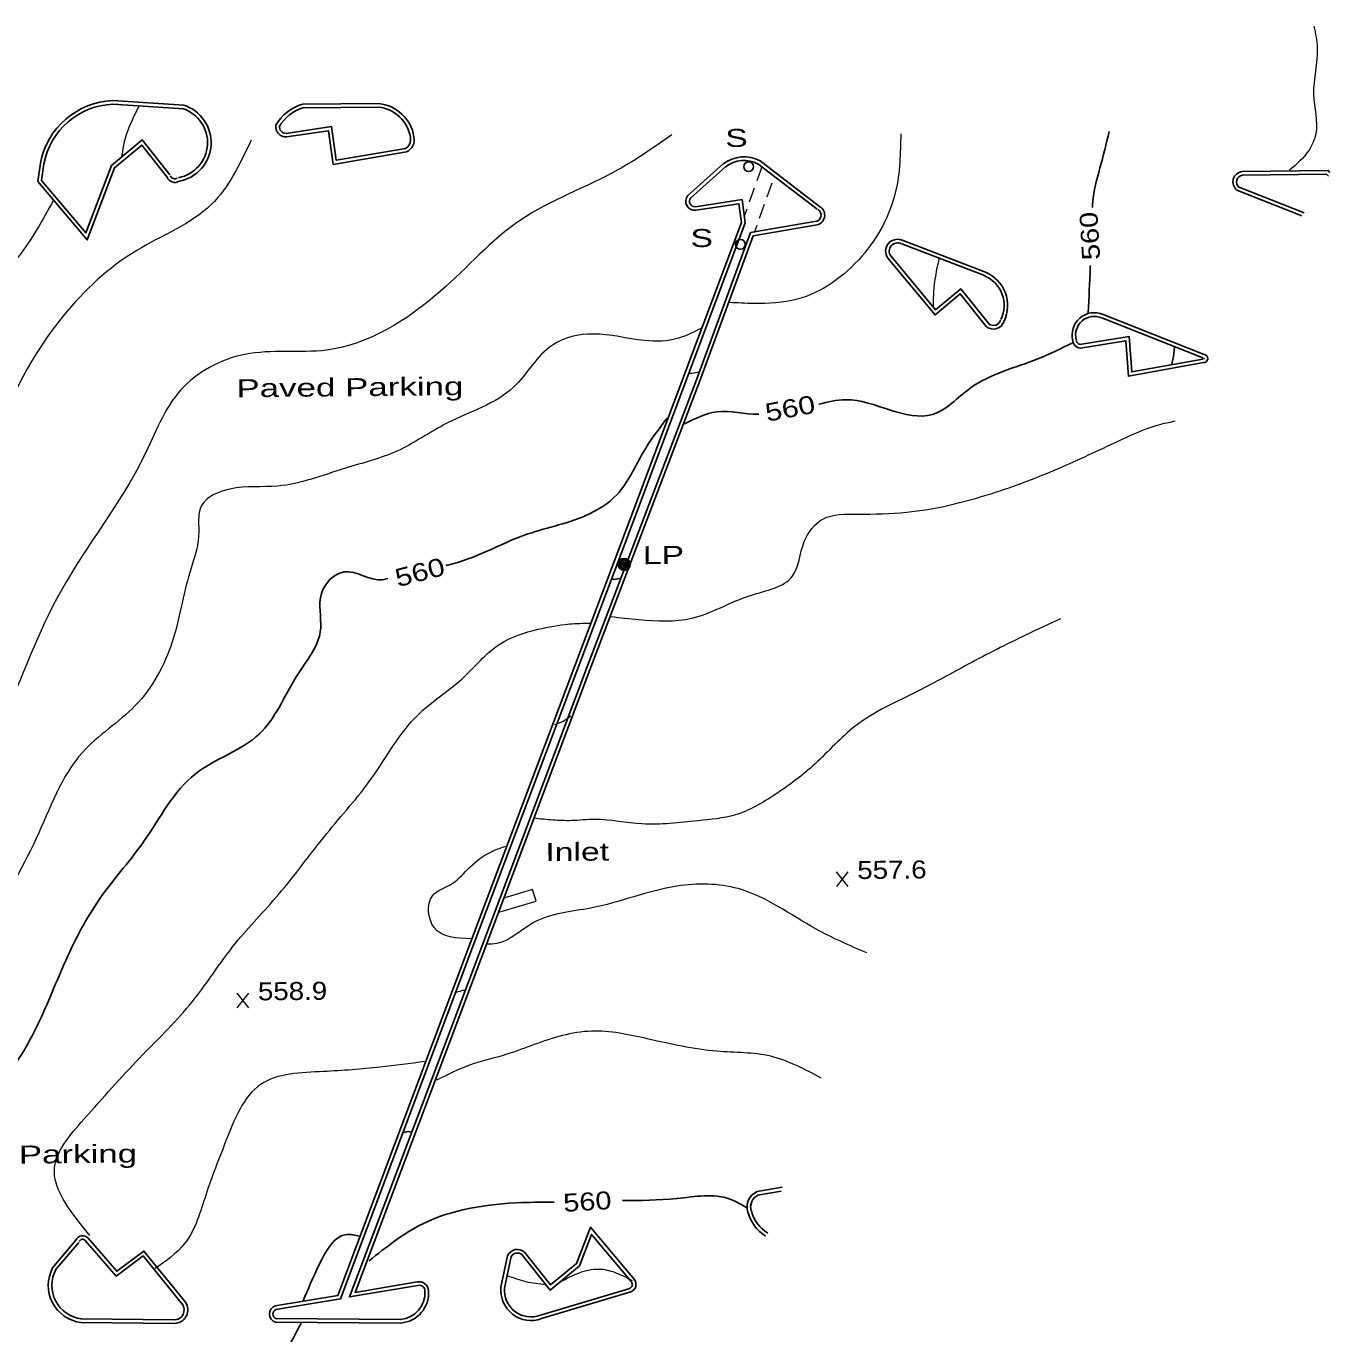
# Model space of a CAD drawing. Extents: x 2361708 to 2370558, y 6977955 to 6991887.
# Drawn here: x 2366902.2 to 2367249.9, y 6987347 to 6987695.7 of the extents above; entities that cross this region are included whole.
import ezdxf
from ezdxf.enums import TextEntityAlignment as Align

# ---------------------------------------------------------------- set-up
doc = ezdxf.new("R2010")
doc.units = 0
doc.header["$LTSCALE"] = 1.9
for name, color, linetype, lineweight in [('13', 7, 'Continuous', 13), ('2', 7, 'Continuous', 25), ('20', 7, 'Continuous', 25), ('21', 7, 'Continuous', 25), ('31', 7, 'Continuous', 13), ('35', 7, 'Continuous', 13), ('9', 7, 'Continuous', 13)]:
    doc.layers.add(name, color=color, linetype=linetype, lineweight=lineweight)

msp = doc.modelspace()

# ---------------------------------------------------------------- linework, layer by layer
at = {"layer": '13'}
for p, q in [((2367097.132, 6987654.501), (2367098.457, 6987658.234)), ((2367095.116, 6987648.841), (2367096.46, 6987652.614)), ((2367099.804, 6987650.136), (2367101.138, 6987653.909)), ((2367097.788, 6987644.477), (2367099.132, 6987648.25)), ((2367093.772, 6987645.068), (2367094.444, 6987646.955)), ((2367096.444, 6987640.704), (2367097.116, 6987642.59))]:
    msp.add_line(p, q, dxfattribs=at)
at = {"layer": '2'}
for p, q in [((2366944.213, 6987674.606), (2366925.361, 6987675.836)), ((2366944.152, 6987673.645), (2366925.3, 6987674.876)), ((2366996.222, 6987675.031), (2366975.973, 6987674.879)), ((2366996.231, 6987674.071), (2366975.981, 6987673.919)), ((2367088.11, 6987658.935), (2367078.69, 6987650.505)), ((2367088.746, 6987658.221), (2367079.326, 6987649.791)), ((2367113.186, 6987646.853), (2367097.32, 6987658.973)), ((2367113.769, 6987647.619), (2367097.903, 6987659.738)), ((2367225.073, 6987651.938), (2367242.389, 6987645.113)), ((2367225.425, 6987652.832), (2367242.991, 6987645.909)), ((2367157.726, 6987629.156), (2367135.725, 6987637.597)), ((2367158.068, 6987630.049), (2367136.066, 6987638.491)), ((2367215.968, 6987607.24), (2367189.035, 6987617.884)), ((2367216.319, 6987608.133), (2367189.387, 6987618.777)), ((2367103.837, 6987386.151), (2367097.178, 6987384.978)), ((2367103.507, 6987385.118), (2367097.347, 6987384.03)), ((2366915.482, 6987372.028), (2366909.253, 6987364.608)), ((2366916.218, 6987371.415), (2366909.988, 6987363.995)), ((2367030.607, 6987367.874), (2367028.827, 6987359.446)), ((2367031.55, 6987367.673), (2367029.769, 6987359.245)), ((2367039.379, 6987352.016), (2367063.192, 6987359.163)), ((2367039.658, 6987351.099), (2367063.471, 6987358.246)), ((2366916.821, 6987350.05), (2366941.715, 6987349.807)), ((2366916.832, 6987351.01), (2366941.726, 6987350.766)), ((2366968.713, 6987350.143), (2367002.117, 6987349.921)), ((2366968.724, 6987351.104), (2367002.128, 6987350.882))]:
    msp.add_line(p, q, dxfattribs=at)
for points in [[(2366971.516, 6987667.085), (2366983.61, 6987668.881), (2366984.905, 6987659.933), (2367003.456, 6987663.08)], [(2366906.95, 6987659.011), (2366906.342, 6987654.525), (2366918.167, 6987640.546), (2366924.946, 6987658.482), (2366933.151, 6987665.351), (2366940.55, 6987656.03)], [(2366971.655, 6987666.137), (2366982.8, 6987667.793), (2366984.096, 6987658.825), (2367003.615, 6987662.131)], [(2366905.999, 6987659.142), (2366905.336, 6987654.235), (2366918.484, 6987638.68), (2366925.752, 6987657.91), (2366933.014, 6987663.979), (2366939.796, 6987655.433)], [(2367249.859, 6987656.695), (2367249.414, 6987657.201), (2367226.486, 6987656.902)], [(2367249.509, 6987655.641), (2367248.983, 6987656.236), (2367226.495, 6987655.942)], [(2367080.807, 6987646.595), (2367092.291, 6987648.334), (2367092.939, 6987643.31), (2367062.344, 6987561.696), (2367020.712, 6987451.394), (2366985.366, 6987357.252), (2366968.622, 6987354.493)], [(2367080.668, 6987647.543), (2367093.12, 6987649.433), (2367093.92, 6987643.2), (2367063.247, 6987561.354), (2367021.615, 6987451.052), (2366986.074, 6987356.399), (2366968.781, 6987353.545)], [(2367006.652, 6987359.935), (2366988.42, 6987356.862), (2367014.348, 6987425.512), (2367051.598, 6987524.411), (2367080.926, 6987601.414), (2367095.394, 6987640.654), (2367112.457, 6987643.586)], [(2367006.493, 6987360.884), (2366989.909, 6987358.086), (2367015.241, 6987425.17), (2367052.491, 6987524.07), (2367081.83, 6987601.072), (2367096.102, 6987639.8), (2367112.616, 6987642.638)], [(2367132.031, 6987633.792), (2367144.575, 6987618.69), (2367151.283, 6987624.274), (2367158.326, 6987615.542)], [(2367132.765, 6987634.409), (2367144.703, 6987620.042), (2367151.419, 6987625.636), (2367159.07, 6987616.148)], [(2367183.742, 6987610.873), (2367196.343, 6987612.923), (2367197.033, 6987603.499), (2367215.991, 6987606.91)], [(2367183.901, 6987609.924), (2367195.464, 6987611.805), (2367196.153, 6987602.36), (2367216.16, 6987605.962)], [(2366944.671, 6987355.485), (2366933.611, 6987369.12), (2366926.382, 6987363.722), (2366918.708, 6987372.538)], [(2367063.575, 6987360.957), (2367052.974, 6987373.567), (2367049.774, 6987365.166), (2367041.925, 6987358.721), (2367034.354, 6987368.189)], [(2367064.309, 6987361.574), (2367052.656, 6987375.434), (2367048.969, 6987365.749), (2367042.072, 6987360.083), (2367035.109, 6987368.786)], [(2366943.927, 6987354.878), (2366933.443, 6987367.799), (2366926.244, 6987362.42), (2366917.984, 6987371.911)]]:
    msp.add_lwpolyline(points, dxfattribs=at)
for centre, radius, start, end in [((2366926.161, 6987655.334), 20.519, 92.23486, 169.30474), ((2366926.161, 6987655.334), 19.559, 92.23486, 169.30474), ((2366941.072, 6987664.62), 9.509, 280.70452, 72.53644), ((2366941.072, 6987664.62), 10.469, 280.70452, 72.53644), ((2366979.236, 6987663.354), 11.978, 105.81197, 150.45573), ((2366979.236, 6987663.354), 11.018, 105.81197, 150.45573), ((2366995.2, 6987664.53), 9.591, 9.16298, 84.4425), ((2366995.2, 6987664.53), 10.551, 9.16298, 84.4425), ((2366971.497, 6987668.847), 2.713, 171.23755, 273.34708), ((2366971.497, 6987668.847), 1.753, 171.23755, 273.34708), ((2367002.064, 6987665.422), 2.678, 295.23741, 12.51175), ((2367002.064, 6987665.422), 3.638, 295.23741, 12.51175), ((2367093.618, 6987651.876), 8.954, 61.41106, 127.96633), ((2367093.618, 6987651.876), 7.994, 61.41106, 127.96633), ((2366941.864, 6987656.226), 2.215, 200.96378, 301.34614), ((2366941.864, 6987656.226), 1.255, 200.96378, 301.34614), ((2367226.803, 6987654.129), 2.791, 96.53229, 231.69698), ((2367226.803, 6987654.129), 1.831, 96.53229, 231.69698), ((2367080.5, 6987648.958), 2.381, 139.48847, 277.39994), ((2367080.5, 6987648.958), 1.421, 139.48847, 277.39994), ((2367112.495, 6987645.289), 1.694, 272.62187, 61.32494), ((2367112.495, 6987645.289), 2.655, 272.62187, 61.32494), ((2367134.583, 6987635.683), 3.175, 62.14387, 216.54513), ((2367134.583, 6987635.683), 2.215, 62.14387, 216.54513), ((2367154.39, 6987621.229), 8.596, 334.03887, 67.36425), ((2367154.39, 6987621.229), 9.556, 334.03887, 67.36425), ((2367160.136, 6987617.896), 2.97, 232.45964, 343.36409), ((2367160.136, 6987617.896), 2.01, 232.45964, 343.36409), ((2367187.025, 6987613.36), 5.91, 66.44284, 195.20793), ((2367187.025, 6987613.36), 4.949, 66.44284, 195.20793), ((2367183.402, 6987611.951), 2.084, 183.87025, 283.82028), ((2367183.402, 6987611.951), 1.124, 183.87025, 283.82028), ((2367216.199, 6987607.051), 1.091, 267.9356, 83.66717), ((2367216.199, 6987607.051), 0.131, 267.9356, 83.66717), ((2367098.848, 6987380.896), 4.41, 112.25071, 198.67688), ((2367098.848, 6987380.896), 3.45, 112.25071, 198.67688), ((2367105.544, 6987382.532), 11.293, 195.6585, 236.99396), ((2367105.544, 6987382.532), 10.333, 195.6585, 237.32319), ((2366917.252, 6987371.307), 1.907, 40.24372, 157.81955), ((2366917.252, 6987371.307), 0.947, 40.24372, 157.81955), ((2367033.181, 6987366.74), 2.811, 46.70518, 156.23488), ((2367033.181, 6987366.74), 1.851, 46.70518, 156.23488), ((2366918.087, 6987359.955), 9.985, 152.22026, 262.72033), ((2366918.087, 6987359.955), 9.025, 152.22026, 262.72033), ((2367001.511, 6987357.923), 7.064, 274.32623, 4.14029), ((2367001.511, 6987357.923), 8.024, 274.32623, 4.14029), ((2367007.016, 6987358.439), 2.501, 1.44868, 102.07585), ((2367007.016, 6987358.439), 1.541, 1.44868, 102.07585), ((2367036.844, 6987358.649), 8.056, 174.31948, 290.43521), ((2367036.844, 6987358.649), 7.096, 174.31948, 290.43521), ((2367062.721, 6987360.204), 1.137, 290.94131, 40.78906), ((2367062.721, 6987360.204), 2.097, 290.94131, 40.78906), ((2366941.691, 6987353.428), 2.662, 270.3796, 34.61374), ((2366941.691, 6987353.428), 3.622, 270.3796, 34.61374), ((2366969.343, 6987352.333), 2.277, 108.47706, 253.93765), ((2366969.343, 6987352.333), 1.317, 108.47706, 253.93765)]:
    msp.add_arc(centre, radius, start, end, dxfattribs=at)
at = {"layer": '20'}
for radius in [1.6, 1.3, 1, 0.539, 0.192]:
    msp.add_circle((2367061.685, 6987552.178), radius, dxfattribs=at)
at = {"layer": '21'}
for centre in [(2367094.867, 6987658.189), (2367092.684, 6987637.508)]:
    msp.add_circle(centre, 1.3, dxfattribs=at)
at = {"layer": '31'}
for p, q in [((2367121.425, 6987466.323), (2367118.308, 6987470.173)), ((2367118.345, 6987466.293), (2367121.388, 6987470.203)), ((2366961.595, 6987433.98), (2366958.478, 6987437.83)), ((2366958.515, 6987433.951), (2366961.558, 6987437.86))]:
    msp.add_line(p, q, dxfattribs=at)
at = {"layer": '31', "lineweight": 25}
for points in [[(2367186.535, 6987647.351), (2367186.55, 6987647.892), (2367188.555, 6987657.891), (2367191.003, 6987667.555)], [(2367185.432, 6987619.29), (2367185.969, 6987631.205), (2367185.993, 6987631.825)], [(2367181.318, 6987611.29), (2367171.958, 6987606.951), (2367153.922, 6987599.139), (2367143.908, 6987592.143), (2367132.667, 6987593.296), (2367120.719, 6987596.092), (2367113.571, 6987594.874)], [(2367208.401, 6987610.078), (2367207.991, 6987606.824), (2367207.625, 6987605.45)], [(2367097.555, 6987592.252), (2367097.525, 6987592.251), (2367086.359, 6987592.835), (2367077.789, 6987589.673)], [(2367073.134, 6987591.179), (2367066.721, 6987581.998), (2367059.767, 6987570.781), (2367051.261, 6987565.13), (2367034.999, 6987559.935), (2367014.634, 6987551.99), (2367014.145, 6987551.886)], [(2366998.667, 6987548.438), (2366997.17, 6987548.104), (2366986.99, 6987550.187), (2366980.954, 6987544.45), (2366980.753, 6987535.147), (2366974.236, 6987522.175), (2366964.4, 6987506.97), (2366947.281, 6987496.267), (2366933.69, 6987478.457), (2366922.547, 6987464.04), (2366913.35, 6987447.861), (2366905.863, 6987430.649), (2366899.581, 6987419.329), (2366892.395, 6987409.43), (2366884.212, 6987392.942), (2366882.5, 6987384.715)], [(2367060.849, 6987548.55), (2367059.042, 6987548.183), (2367058.372, 6987548.227)], [(2367002.386, 6987400.487), (2367004.052, 6987400.942), (2367004.892, 6987400.821)], [(2367061.239, 6987382.556), (2367075.685, 6987383.114), (2367089.927, 6987382.959), (2367094.671, 6987380.424)], [(2366993.698, 6987366.542), (2367007.816, 6987376.287), (2367034.393, 6987382.031), (2367043.052, 6987382.163)], [(2366976.059, 6987355.864), (2366980.387, 6987365.525), (2366987.661, 6987373.545), (2366991.076, 6987373.088)], [(2366926.299, 6987301.968), (2366933.8, 6987308.299), (2366942.417, 6987313.841), (2366954.931, 6987325.091), (2366967.668, 6987337.063), (2366974.515, 6987347.899), (2366975.576, 6987349.919)]]:
    msp.add_spline(points, degree=3, dxfattribs=at)
at = {"layer": '35'}
for points in [[(2367245.597, 6987695.676), (2367246.513, 6987689.854), (2367245.521, 6987677.465), (2367246.101, 6987666.939), (2367244.302, 6987662.632), (2367239.033, 6987657.212)], [(2366927.752, 6987661.009), (2366928.793, 6987666.179), (2366931.639, 6987672.956), (2366932.473, 6987674.635)], [(2366962.193, 6987665.247), (2366951.566, 6987648.095), (2366931.702, 6987635.865), (2366912.186, 6987618.538), (2366893.693, 6987584.071), (2366886.805, 6987557.564), (2366874.225, 6987527.003), (2366852.343, 6987481.902), (2366841.839, 6987453.911), (2366827.629, 6987426.545), (2366819.425, 6987401.725), (2366810.01, 6987380.115), (2366805.898, 6987368.695), (2366805.84, 6987364.314)], [(2367074.385, 6987666.695), (2367059.973, 6987657.327), (2367034.03, 6987643.97), (2367012.669, 6987624.995), (2366982.287, 6987609.305), (2366960.497, 6987608.148), (2366943.387, 6987598.605), (2366933.614, 6987581.001), (2366911.632, 6987545.35), (2366895.769, 6987509.897), (2366872.67, 6987462.445), (2366858.133, 6987430.505), (2366838.439, 6987387.716), (2366829.522, 6987362.119), (2366825.847, 6987354.304)], [(2367135.435, 6987666.996), (2367134.072, 6987651.592), (2367125.016, 6987634.315), (2367107.784, 6987622.86), (2367096.224, 6987621.731), (2367089.782, 6987621.989)], [(2366909.445, 6987649.124), (2366900.196, 6987634.246), (2366885.97, 6987617.939), (2366873.062, 6987589.285), (2366866.828, 6987560.264), (2366849.849, 6987520.08), (2366837.508, 6987490.752), (2366823.99, 6987467.362), (2366810.775, 6987437.324), (2366798.604, 6987405.927), (2366789.235, 6987378.427), (2366779.624, 6987349.084), (2366770.342, 6987326.074), (2366758.913, 6987312.295), (2366747.82, 6987308.309), (2366736.556, 6987290.861), (2366728.049, 6987277.899), (2366722.622, 6987272.378)], [(2367145.67, 6987633.942), (2367144.358, 6987626.829), (2367144.072, 6987622.216), (2367144.026, 6987620.715)], [(2367082.147, 6987615.086), (2367076.192, 6987612.469), (2367067.077, 6987611.843), (2367053.36, 6987613.602), (2367042.547, 6987610.659), (2367032.134, 6987599.399), (2367014.573, 6987589.892), (2367001.034, 6987582.352), (2366987.327, 6987577.822), (2366969.231, 6987573.05), (2366956.548, 6987572.249), (2366948.99, 6987567.866), (2366948.197, 6987559.698), (2366945.849, 6987550.035), (2366941.175, 6987531.54), (2366931.296, 6987514.535), (2366917.205, 6987502.051), (2366904.893, 6987479.062), (2366891.784, 6987454.687), (2366879.76, 6987429.931), (2366870.845, 6987410.405), (2366861.204, 6987382.002), (2366853.616, 6987359.739), (2366847.313, 6987345.338), (2366840.573, 6987325.383), (2366834.663, 6987307.425), (2366818.675, 6987284.072), (2366811.201, 6987268.71), (2366803.713, 6987244.228), (2366800.597, 6987229.128), (2366793.138, 6987202.705), (2366791.453, 6987182.158), (2366791.663, 6987166.45), (2366790.46, 6987138.337), (2366790.825, 6987115.759), (2366790.764, 6987090.637), (2366787.121, 6987063.661), (2366786.887, 6987040.978), (2366797.799, 6987034.512), (2366817.783, 6987041.522), (2366833.171, 6987051.259), (2366843.853, 6987063.761), (2366853.183, 6987082.691), (2366857.498, 6987096.913), (2366863.384, 6987109.969), (2366867.227, 6987113.846)], [(2367081.637, 6987603.501), (2367079.74, 6987603.112), (2367078.851, 6987603.094)], [(2367058.156, 6987538.264), (2367065.615, 6987537.455), (2367079.682, 6987537.829), (2367095.345, 6987543.898), (2367106.518, 6987548.965), (2367109.709, 6987558.246), (2367114.692, 6987564.264), (2367123.82, 6987565.6), (2367137.016, 6987566.086), (2367159.5, 6987571.021), (2367178.473, 6987578.191), (2367194.453, 6987585.534), (2367204.865, 6987589.593), (2367208.618, 6987590.419)], [(2366919.2, 6987373.284), (2366913.54, 6987380.63), (2366909.727, 6987390.434), (2366917.606, 6987404.23), (2366932.431, 6987420.571), (2366945.777, 6987434.669), (2366958.061, 6987451.207), (2366969.488, 6987464.156), (2366982.295, 6987480.319), (2366994.403, 6987495.255), (2367006.644, 6987512.023), (2367018.443, 6987521.705), (2367028.495, 6987530.911), (2367038.718, 6987534.869), (2367047.085, 6987536.288), (2367052.603, 6987536.521)], [(2367178.018, 6987537.705), (2367168.739, 6987533.326), (2367153.403, 6987525.54), (2367140.02, 6987518.412), (2367123.278, 6987509.053), (2367112.573, 6987498.99), (2367101.96, 6987490.839), (2367091.282, 6987485.387), (2367081.366, 6987483.832), (2367066.404, 6987482.97), (2367053.892, 6987484.171), (2367047.624, 6987483.861), (2367042.712, 6987484.004), (2367037.557, 6987484.496)], [(2367043.15, 6987509.5), (2367045.451, 6987510.422), (2367047.479, 6987511.761)], [(2367020.983, 6987452.376), (2367010.983, 6987455.381), (2367010.543, 6987463.787), (2367015.812, 6987467.088), (2367020.521, 6987471.453), (2367026.77, 6987475.803), (2367030.038, 6987477.064)], [(2367126.374, 6987448.599), (2367112.893, 6987454.931), (2367092.069, 6987465.733), (2367075.762, 6987466.388), (2367052.746, 6987460.549), (2367037.542, 6987456.664), (2367027.765, 6987451.13), (2367025.017, 6987450.904)], [(2367019.194, 6987438.608), (2367017.377, 6987438.211), (2367016.82, 6987437.986)], [(2367114.241, 6987415.182), (2367100.745, 6987421.034), (2367086.471, 6987422.388), (2367067.819, 6987425.711), (2367052.939, 6987427.739), (2367037.662, 6987424.154), (2367030.376, 6987421.564), (2367020.453, 6987418.66), (2367011.661, 6987414.695)], [(2367008.574, 6987419.627), (2366996.537, 6987418.152), (2366981.458, 6987416.958), (2366964.709, 6987413.529), (2366955.404, 6987398.28), (2366950.188, 6987384.249), (2366944.453, 6987371.084), (2366936.545, 6987364.418)], [(2367030.457, 6987362.592), (2367035.473, 6987360.99), (2367040.771, 6987360.19)], [(2367044.257, 6987360.653), (2367050.34, 6987363.531), (2367055.513, 6987364.29), (2367059.633, 6987363.25), (2367063.792, 6987361.279)]]:
    msp.add_spline(points, degree=3, dxfattribs=at)
at = {"layer": '9'}
msp.add_lwpolyline([(2367028.296, 6987459.416), (2367038.168, 6987462.37), (2367037.228, 6987465.501), (2367029.889, 6987463.301)], dxfattribs=at)

# ---------------------------------------------------------------- texts
at = {"layer": '2', "width": 1.45}
for p in [(2366958.295, 6987596.726), (2366871.288, 6987392.148)]:
    msp.add_text('Paved Parking', height=4.8, rotation=0.545, dxfattribs=at).set_placement(p)
at = {"layer": '20', "width": 1.4}
msp.add_text('  LP', height=4.8, rotation=0.545, dxfattribs=at).set_placement((2367061.685, 6987552.178))
at = {"layer": '21', "width": 1.4}
for p in [(2367083.657, 6987663.403), (2367074.39, 6987636.713)]:
    msp.add_text('  S', height=4.8, rotation=0.545, dxfattribs=at).set_placement(p)
at = {"layer": '31'}
for rotation, width, p in [(93.442, 1.2, (2367188.236, 6987639.884)), (10.592, 1.25, (2367106.361, 6987591.424)), (14.633, 1.25, (2367007.803, 6987547.77)), (3.504, 1.2, (2367052.002, 6987379.929))]:
    msp.add_text(' 560 ', height=4.8, rotation=rotation, dxfattribs=dict(at, width=width)).set_placement(p, align=Align.CENTER)
at = {"layer": '31', "width": 1.15}
for s, p in [('557.6', (2367123.866, 6987468.287)), ('558.9', (2366964.036, 6987435.943))]:
    msp.add_text(s, height=4.8, rotation=0.545, dxfattribs=at).set_placement(p)
at = {"layer": '9', "width": 1.4}
msp.add_text('Inlet', height=4.8, rotation=0.545, dxfattribs=at).set_placement((2367040.686, 6987473.075))

doc.saveas('drawing.dxf')
